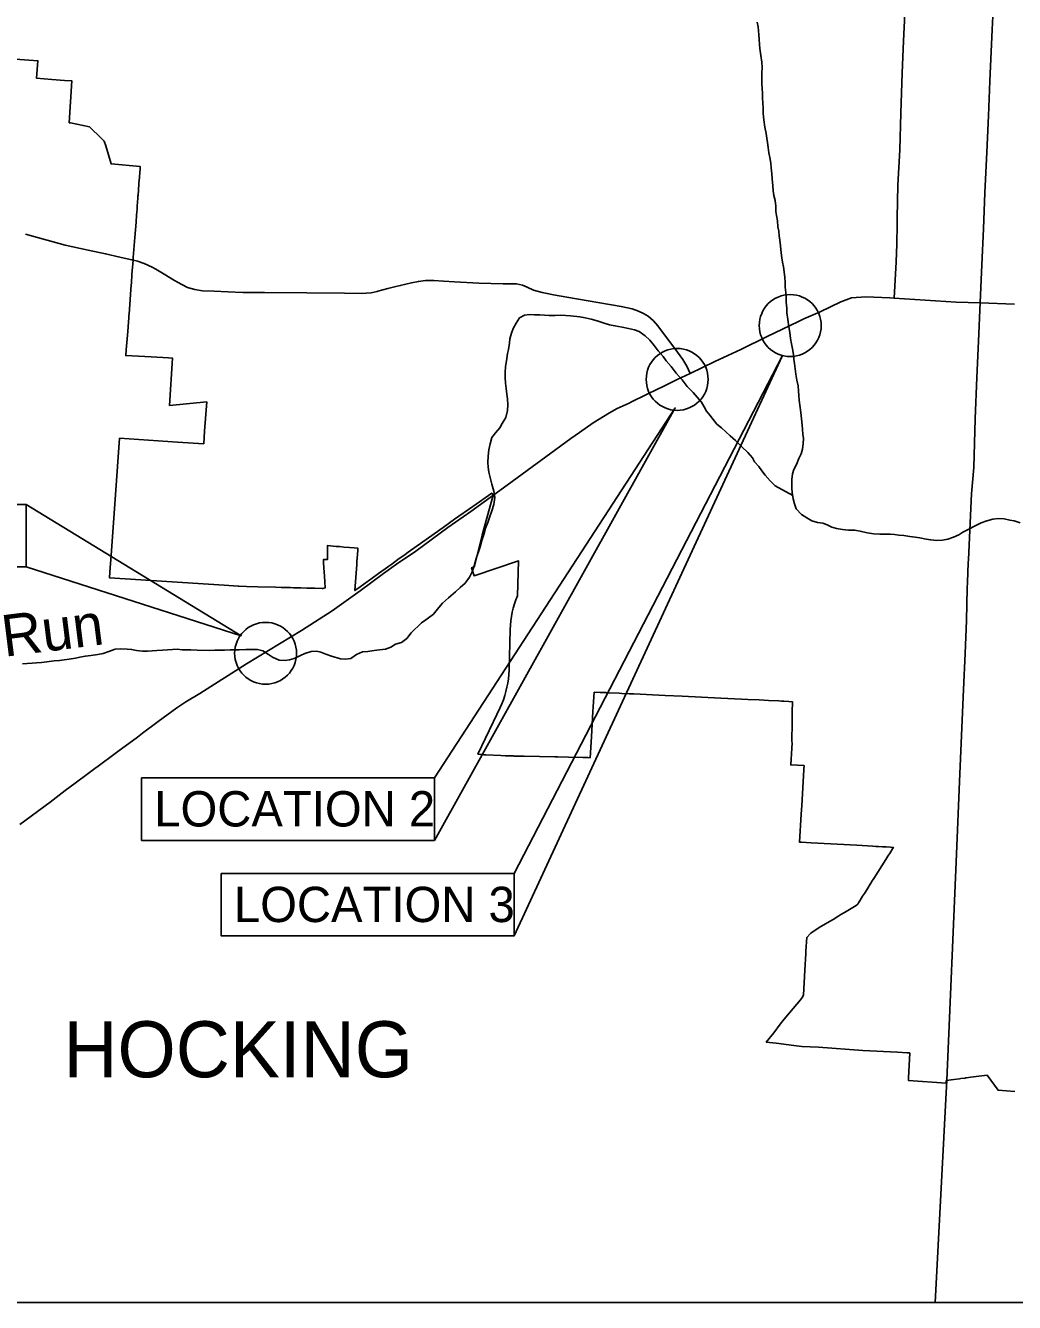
# Model space of a CAD drawing. Extents: x 0 to 34, y 0 to 22.
# Drawn here: x 4.86 to 9.62, y 8.99 to 15.13 of the extents above; entities that cross this region are included whole.
import ezdxf

# ---------------------------------------------------------------- set-up
doc = ezdxf.new("R2010")
doc.units = 0
for name, color, linetype in [('BR_P_Gen_Text', 7, 'Continuous'), ('Default', 7, 'Continuous'), ('GM_X_Corporation', 7, 'Continuous'), ('GM_X_Major_River', 7, 'Continuous'), ('GM_X_Minor_River', 7, 'Continuous'), ('GM_X_Minor_River_Text', 7, 'Continuous'), ('GM_X_State_Route', 7, 'Continuous'), ('GM_X_Township', 7, 'Continuous'), ('GM_X_Township_Text', 7, 'Continuous'), ('GM_X_US_Route', 7, 'Continuous'), ('SH_Text', 7, 'Continuous')]:
    doc.layers.add(name, color=color, linetype=linetype)

msp = doc.modelspace()

# ---------------------------------------------------------------- linework, layer by layer
at = {"layer": 'BR_P_Gen_Text'}
for points in [[(7.2085, 11.0538), (7.2085, 10.7536), (8.4986, 13.5428)], [(6.8251, 11.5138), (6.8251, 11.2136), (7.9848, 13.2947)], [(3.4525, 12.8303), (4.8613, 12.8303), (4.8613, 12.53), (3.4525, 12.53)], [(4.8613, 12.8303), (4.8613, 12.53), (5.8958, 12.1979)], [(5.4164, 11.5138), (6.8251, 11.5138), (6.8251, 11.2136), (5.4164, 11.2136)], [(5.7998, 11.0538), (7.2085, 11.0538), (7.2085, 10.7536), (5.7998, 10.7536)]]:
    msp.add_lwpolyline(points, close=True, dxfattribs=at)
at = {"layer": 'Default'}
for centre in [(8.5378, 13.6907), (7.9936, 13.4317), (6.0129, 12.1137)]:
    msp.add_circle(centre, 0.149, dxfattribs=at)
at = {"layer": 'GM_X_Corporation'}
msp.add_lwpolyline([(9.6181, 10.005), (9.5385, 10.0112), (9.4849, 10.0836), (9.4195, 10.0753), (9.3826, 10.0704), (9.3791, 10.07), (9.3592, 10.0673), (9.353, 10.0665), (9.3247, 10.0628), (9.2888, 10.0581), (9.2885, 10.0512), (9.2882, 10.0461), (9.107, 10.0584), (9.1076, 10.0704), (9.1131, 10.1912), (9.103, 10.1917), (9.1012, 10.1918), (9.0534, 10.1941), (8.8874, 10.2022), (8.6737, 10.2188), (8.5939, 10.2223), (8.5547, 10.2271), (8.47, 10.2373), (8.4385, 10.2412), (8.4224, 10.2431), (8.4593, 10.2878), (8.49, 10.3289), (8.4956, 10.3365), (8.5004, 10.3429), (8.5346, 10.3839), (8.587, 10.4467), (8.595, 10.4577), (8.6025, 10.4681), (8.6089, 10.5889), (8.6131, 10.6693), (8.6137, 10.6815), (8.6172, 10.747), (8.6351, 10.7654), (8.6374, 10.7677), (8.6441, 10.772), (8.6857, 10.7985), (8.6995, 10.8068), (8.7264, 10.823), (8.7439, 10.8336), (8.7712, 10.8499), (8.7822, 10.8566), (8.7994, 10.8669), (8.8479, 10.8961), (8.8607, 10.9038), (8.8625, 10.9066), (8.867, 10.9138), (8.8723, 10.9223), (8.8864, 10.9449), (8.895, 10.9586), (8.9059, 10.9762), (8.9223, 11.0024), (8.9256, 11.0077), (8.9289, 11.0129), (8.9295, 11.0139), (8.9402, 11.0307), (8.9594, 11.0611), (8.9787, 11.0914), (8.998, 11.1218), (9.0077, 11.1371), (9.0182, 11.1536), (9.0299, 11.1721), (9.0348, 11.1798), (9.021, 11.1806), (8.9995, 11.1818), (8.9826, 11.1827), (8.9628, 11.1839), (8.959, 11.1841), (8.9572, 11.1842), (8.9546, 11.1843), (8.9517, 11.1845), (8.9498, 11.1856), (8.9492, 11.1846), (8.936, 11.1854), (8.8578, 11.1898), (8.6392, 11.202), (8.5915, 11.2044), (8.5829, 11.2049), (8.5909, 11.3404), (8.5933, 11.382), (8.6034, 11.5526), (8.6036, 11.5558), (8.6043, 11.5733), (8.5405, 11.5766), (8.5458, 11.6575), (8.5474, 11.6818), (8.5457, 11.6906), (8.545, 11.6938), (8.5466, 11.7777), (8.5474, 11.8307), (8.5482, 11.8809), (8.5482, 11.8809), (8.531, 11.8818), (8.5073, 11.8831), (8.4953, 11.8837), (8.4833, 11.8843), (8.4335, 11.8869), (8.389, 11.8893), (8.3338, 11.8917), (8.3029, 11.8933), (8.2033, 11.8981), (8.0171, 11.9072), (7.9353, 11.9112), (7.7846, 11.9185), (7.7646, 11.9194), (7.7278, 11.921), (7.7143, 11.9216), (7.6664, 11.9236), (7.6594, 11.9239), (7.6544, 11.9241), (7.6497, 11.9243), (7.6425, 11.9246), (7.6238, 11.9254), (7.5946, 11.9267), (7.5932, 11.9047), (7.5917, 11.8809), (7.5902, 11.8569), (7.5886, 11.833), (7.581, 11.7117), (7.5747, 11.6115), (7.5636, 11.6117), (7.5403, 11.6122), (7.4715, 11.6137), (7.419, 11.6149), (7.4123, 11.615), (7.4054, 11.6152), (7.3305, 11.6169), (7.2579, 11.6185), (7.2288, 11.6191), (7.2192, 11.6193), (7.2144, 11.6194), (7.2098, 11.6195), (7.2037, 11.6197), (7.2, 11.6197), (7.1854, 11.6201), (7.1787, 11.6203), (7.1654, 11.6209), (7.1455, 11.6217), (7.0725, 11.6251), (7.0625, 11.6256), (7.0563, 11.6263), (7.0492, 11.6271), (7.0348, 11.6288), (7.108, 11.7825), (7.1097, 11.7861), (7.1412, 11.8523), (7.1497, 11.8712), (7.1572, 11.8905), (7.1639, 11.9101), (7.1697, 11.9301), (7.1745, 11.9502), (7.1785, 11.9706), (7.1814, 11.9912), (7.1834, 12.0118), (7.1845, 12.0325), (7.1904, 12.2282), (7.1915, 12.2491), (7.1935, 12.2699), (7.1965, 12.2906), (7.2003, 12.3111), (7.2051, 12.3315), (7.2108, 12.3516), (7.2174, 12.3714), (7.2249, 12.3909), (7.2304, 12.5581), (7.0166, 12.4871), (7.0103, 12.506), (7.004, 12.525), (7.0161, 12.529), (7.0275, 12.5738), (7.0486, 12.6569), (7.0554, 12.6816), (7.0623, 12.7064), (7.1039, 12.8572), (7.1075, 12.8702), (7.108, 12.8721), (7.11, 12.8735), (7.101, 12.8846), (7.0106, 12.8206), (6.9226, 12.7584), (6.8673, 12.7193), (6.7428, 12.6312), (6.7425, 12.631), (6.7422, 12.6308), (6.7109, 12.6084), (6.7107, 12.6082), (6.7105, 12.6081), (6.7103, 12.608), (6.6993, 12.6001), (6.6923, 12.595), (6.6825, 12.588), (6.6709, 12.5797), (6.6495, 12.5643), (6.628, 12.5489), (6.6197, 12.5429), (6.6066, 12.5335), (6.6001, 12.5288), (6.5888, 12.5207), (6.5886, 12.5205), (6.5884, 12.5204), (6.5882, 12.5203), (6.5569, 12.4978), (6.5567, 12.4976), (6.5565, 12.4975), (6.5563, 12.4974), (6.5259, 12.4755), (6.5083, 12.4629), (6.5034, 12.459), (6.4862, 12.4457), (6.4685, 12.4335), (6.4426, 12.4156), (6.4516, 12.5406), (6.4517, 12.5431), (6.4524, 12.5527), (6.4542, 12.5768), (6.4547, 12.5848), (6.4569, 12.615), (6.4572, 12.6194), (6.4394, 12.6209), (6.4171, 12.6228), (6.3901, 12.625), (6.3679, 12.6269), (6.3521, 12.6282), (6.3104, 12.6317), (6.3107, 12.6098), (6.3108, 12.6052), (6.3112, 12.5658), (6.2913, 12.5643), (6.2922, 12.5483), (6.2935, 12.5252), (6.2957, 12.4847), (6.2973, 12.4572), (6.2989, 12.4287), (6.2877, 12.4255), (6.2861, 12.4255), (6.2846, 12.4256), (6.2506, 12.4265), (6.2128, 12.4275), (6.211, 12.4276), (6.1827, 12.4284), (6.1822, 12.4284), (6.1647, 12.4289), (6.1467, 12.4294), (6.1326, 12.4298), (6.1311, 12.4298), (6.1228, 12.43), (6.0987, 12.4307), (6.0884, 12.431), (6.0604, 12.4318), (5.9748, 12.4341), (5.9215, 12.4356), (5.8836, 12.4367), (5.8814, 12.4367), (5.8141, 12.4411), (5.2611, 12.4775), (5.2631, 12.5042), (5.2691, 12.5865), (5.2906, 12.8769), (5.3103, 13.1485), (5.5889, 13.1303), (5.7149, 13.1223), (5.7193, 13.183), (5.7208, 13.2037), (5.7296, 13.3236), (5.5511, 13.3057), (5.5645, 13.5345), (5.5461, 13.5354), (5.4624, 13.5395), (5.4015, 13.5429), (5.3401, 13.5463), (5.3423, 13.5739), (5.3492, 13.6627), (5.3528, 13.708), (5.3542, 13.7255), (5.355, 13.7364), (5.3573, 13.7653), (5.3576, 13.7696), (5.3663, 13.8872), (5.3668, 13.894), (5.3699, 13.936), (5.3751, 14.006), (5.376, 14.0176), (5.3835, 14.114), (5.3893, 14.188), (5.392, 14.2233), (5.3929, 14.235), (5.3942, 14.2532), (5.3953, 14.2665), (5.3965, 14.283), (5.3982, 14.3055), (5.3988, 14.3129), (5.3992, 14.3184), (5.4011, 14.3428), (5.4033, 14.3727), (5.4036, 14.3763), (5.4056, 14.4025), (5.4076, 14.4289), (5.4087, 14.4435), (5.4097, 14.4556), (5.2703, 14.4688), (5.2437, 14.5549), (5.2367, 14.5776), (5.2229, 14.5911), (5.1662, 14.6462), (5.0739, 14.6656), (5.0682, 14.6668), (5.0807, 14.8675), (5.0449, 14.8704), (4.9835, 14.8752), (4.911, 14.8809), (4.9172, 14.9647), (4.7663, 14.9757)], dxfattribs=at)
at = {"layer": 'GM_X_Major_River'}
for points in [[(8.5131, 13.8989), (8.5122, 13.9213), (8.5081, 13.9493), (8.5049, 13.9732), (8.5, 13.9956), (8.4968, 14.0164), (8.4943, 14.0412), (8.4903, 14.074), (8.4878, 14.1012), (8.4853, 14.122), (8.4829, 14.1452), (8.4788, 14.1659), (8.4764, 14.1947), (8.4723, 14.2195), (8.4691, 14.2395), (8.4682, 14.2651), (8.4649, 14.2923), (8.4593, 14.3171), (8.456, 14.3395), (8.4536, 14.3626), (8.4503, 14.3962), (8.4486, 14.421), (8.4462, 14.4498), (8.4445, 14.4722), (8.4396, 14.4994), (8.4348, 14.521), (8.4315, 14.5482), (8.4291, 14.5714), (8.4258, 14.5921), (8.4218, 14.6153), (8.4153, 14.6449), (8.4104, 14.6809), (8.4072, 14.7105), (8.4071, 14.7369), (8.4054, 14.7625), (8.4046, 14.7849), (8.4037, 14.808), (8.4028, 14.8336), (8.4012, 14.8536), (8.401, 14.9064), (8.4026, 14.932), (8.4009, 14.9584), (8.3968, 14.9904), (8.392, 15.0232), (8.3903, 15.0432), (8.3886, 15.068), (8.3862, 15.0888), (8.3829, 15.1288), (8.3788, 15.1503)], [(9.6442, 12.741), (9.6155, 12.7506), (9.594, 12.7545), (9.5668, 12.76), (9.5397, 12.7623), (9.5134, 12.7598), (9.4848, 12.7517), (9.4561, 12.742), (9.425, 12.7259), (9.398, 12.7114), (9.3693, 12.6962), (9.3486, 12.6841), (9.3232, 12.6728), (9.2961, 12.6623), (9.2706, 12.6574), (9.2427, 12.6565), (9.214, 12.6596), (9.1917, 12.6636), (9.1614, 12.6691), (9.139, 12.673), (9.1135, 12.6761), (9.084, 12.68), (9.0609, 12.6823), (9.0402, 12.6847), (9.0194, 12.6862), (8.9987, 12.6869), (8.9684, 12.6876), (8.9397, 12.6891), (8.9078, 12.6938), (8.8743, 12.7017), (8.8472, 12.7064), (8.8185, 12.7063), (8.7898, 12.7087), (8.7611, 12.715), (8.7387, 12.7213), (8.7164, 12.7324), (8.6948, 12.7395), (8.6685, 12.7427), (8.6422, 12.7514), (8.6182, 12.7649), (8.5927, 12.7816), (8.5671, 12.8087), (8.5583, 12.8335), (8.5526, 12.8575), (8.5478, 12.8871), (8.5461, 12.9078), (8.5453, 12.9278), (8.5452, 12.9494), (8.5491, 12.9767), (8.5554, 12.9975), (8.5673, 13.0215), (8.58, 13.0503), (8.5903, 13.0736), (8.5974, 13.096), (8.6005, 13.1224), (8.6012, 13.1472), (8.5988, 13.168), (8.5963, 13.1912), (8.5955, 13.2112), (8.5914, 13.2424), (8.5889, 13.2728), (8.5857, 13.2968), (8.5816, 13.3319), (8.5791, 13.3543), (8.5783, 13.3743), (8.5758, 13.3999), (8.5702, 13.4279), (8.5645, 13.4575), (8.5612, 13.4823), (8.558, 13.5087), (8.5547, 13.5286), (8.5531, 13.5502), (8.5498, 13.571), (8.5434, 13.6022), (8.5393, 13.6286), (8.5353, 13.6566), (8.5312, 13.6838), (8.5263, 13.7197), (8.5222, 13.7525), (8.5214, 13.7741), (8.5189, 13.8037), (8.5188, 13.8269), (8.5172, 13.8501), (8.5139, 13.8757), (8.5131, 13.8989)]]:
    msp.add_lwpolyline(points, dxfattribs=at)
at = {"layer": 'GM_X_Minor_River'}
for points in [[(6.7631, 12.2607), (6.7846, 12.2743), (6.8212, 12.3023), (6.8459, 12.3335), (6.8651, 12.3544), (6.8937, 12.3808), (6.9264, 12.4096), (6.9487, 12.4296), (6.9734, 12.4505), (6.9949, 12.4793), (7.0077, 12.5049), (7.0172, 12.5353), (7.0268, 12.5705), (7.0451, 12.6257), (7.0531, 12.6569), (7.0634, 12.6857), (7.0706, 12.7153), (7.0817, 12.7425), (7.0929, 12.7713), (7.1024, 12.7985), (7.1112, 12.8297), (7.116, 12.8633), (7.112, 12.8937), (7.1016, 12.9273), (7.0936, 12.9593), (7.088, 12.9849), (7.0848, 13.0088), (7.0832, 13.032), (7.084, 13.0624), (7.088, 13.092), (7.0935, 13.1216), (7.1023, 13.152), (7.119, 13.1744), (7.1397, 13.1993), (7.1517, 13.2201), (7.1684, 13.2489), (7.1764, 13.2817), (7.1788, 13.3097), (7.1772, 13.3385), (7.174, 13.36), (7.17, 13.388), (7.1668, 13.4128), (7.1652, 13.44), (7.166, 13.4664), (7.1675, 13.4928), (7.1747, 13.5328), (7.1779, 13.556), (7.1826, 13.576), (7.1874, 13.6056), (7.189, 13.6264), (7.197, 13.6544), (7.2049, 13.676), (7.2185, 13.7024), (7.2344, 13.7272), (7.2583, 13.74), (7.283, 13.7441), (7.3069, 13.7417), (7.3332, 13.7417), (7.3556, 13.7401), (7.3771, 13.7394), (7.4058, 13.7394), (7.4345, 13.7402), (7.4807, 13.7379), (7.5246, 13.7323), (7.5517, 13.7276), (7.5804, 13.7212), (7.6083, 13.7132), (7.6417, 13.7029), (7.6688, 13.6941), (7.6944, 13.6901), (7.7286, 13.683), (7.7597, 13.6758), (7.7876, 13.6694), (7.8115, 13.6623), (7.8394, 13.6407), (7.8626, 13.6199), (7.8833, 13.5944), (7.9017, 13.5696), (7.9256, 13.5424), (7.9407, 13.5217), (7.9647, 13.4937), (7.9894, 13.4617), (8.0173, 13.4298), (8.0412, 13.3978), (8.0715, 13.3691), (8.0907, 13.3467), (8.1114, 13.3227), (8.1234, 13.3003), (8.1353, 13.2795), (8.1513, 13.2588), (8.1672, 13.238), (8.1848, 13.2164), (8.2071, 13.198), (8.2486, 13.1597), (8.2741, 13.1381), (8.3052, 13.1078), (8.3339, 13.0806), (8.3562, 13.0543), (8.3658, 13.0343), (8.3873, 13.0119), (8.4017, 12.9919)], [(8.4017, 12.9919), (8.4176, 12.9703), (8.4407, 12.9432), (8.4647, 12.92), (8.5501, 12.8726)], [(6.1066, 12.0784), (6.1274, 12.0823), (6.1506, 12.0885), (6.1803, 12.1034), (6.2019, 12.112), (6.2323, 12.1222), (6.2587, 12.1235), (6.2794, 12.1185), (6.3024, 12.1095), (6.3303, 12.1004), (6.3732, 12.0872), (6.398, 12.0854), (6.4235, 12.0883), (6.4508, 12.1073), (6.4797, 12.1207), (6.5045, 12.1228), (6.5348, 12.1266), (6.5612, 12.1311), (6.5907, 12.1333), (6.6156, 12.1434), (6.6381, 12.1577), (6.6669, 12.1662), (6.6934, 12.1852), (6.7136, 12.2115), (6.7631, 12.2607)], [(4.8431, 12.0629), (4.8655, 12.0651), (4.8887, 12.0665), (4.911, 12.0679), (4.935, 12.0693), (4.9597, 12.0722), (4.9949, 12.0775), (5.0205, 12.0797), (5.0428, 12.0827), (5.0668, 12.0857), (5.098, 12.0902), (5.1196, 12.0948), (5.146, 12.1002), (5.1723, 12.1039), (5.2059, 12.1084), (5.2307, 12.1122), (5.2587, 12.1224), (5.2883, 12.1341), (5.3147, 12.1347), (5.3466, 12.1336), (5.3681, 12.1326), (5.392, 12.1275), (5.4207, 12.1241), (5.4447, 12.1238), (5.4894, 12.1266), (5.5173, 12.1288), (5.5413, 12.1302), (5.5645, 12.1323), (5.5868, 12.1329), (5.6115, 12.1311), (5.6323, 12.1301), (5.6538, 12.1299), (5.6833, 12.128), (5.7408, 12.1275), (5.7679, 12.1281), (5.7935, 12.1294), (5.815, 12.1292), (5.8421, 12.1298), (5.8645, 12.1304), (5.886, 12.131), (5.9172, 12.1315), (5.9475, 12.132), (5.9738, 12.1326), (5.9993, 12.1259), (6.0263, 12.108), (6.0469, 12.095), (6.0779, 12.0803), (6.1066, 12.0784)]]:
    msp.add_lwpolyline(points, dxfattribs=at)
at = {"layer": 'GM_X_State_Route'}
for p in [(9.0168, 13.8239), (9.3361, 13.8036)]:
    msp.add_line(p, (9.0373, 13.8231), dxfattribs=at)
for points in [[(9.0531, 14.2085), (9.055, 14.3656), (9.0658, 14.5364), (9.0701, 14.7127), (9.0762, 14.9069), (9.0828, 15.0593), (9.0937, 15.2928), (9.0966, 15.4368), (9.0985, 15.4757)], [(9.0373, 13.8231), (9.0472, 13.9972), (9.0512, 14.0825), (9.0528, 14.1792), (9.0531, 14.2085)], [(4.8569, 14.1299), (5.0476, 14.0772), (5.1597, 14.0535), (5.2428, 14.0361), (5.3121, 14.0199), (5.3614, 14.0089)], [(5.3614, 14.0089), (5.3697, 14.0071), (5.3969, 14.0003), (5.4293, 13.9895), (5.4663, 13.9724), (5.4845, 13.9616), (5.5254, 13.9383), (5.5737, 13.9082), (5.6095, 13.8877), (5.6367, 13.8739), (5.6725, 13.864), (5.7088, 13.8584), (5.7658, 13.8565), (5.8309, 13.8527), (5.9038, 13.8504), (6.0071, 13.8493), (6.2121, 13.8478), (6.3921, 13.8463), (6.4724, 13.8455), (6.5213, 13.8485), (6.5498, 13.8551)], [(6.5498, 13.8551), (6.5538, 13.856), (6.6018, 13.8683), (6.6335, 13.8763), (6.661, 13.8828), (6.7147, 13.8961), (6.7485, 13.9034), (6.7829, 13.9076), (6.8227, 13.9082), (6.8686, 13.9046), (6.9217, 13.9003), (7.0392, 13.8947), (7.1569, 13.8915), (7.2208, 13.8913), (7.2495, 13.8843), (7.272, 13.8752), (7.3018, 13.8617), (7.344, 13.8493), (7.3608, 13.8459), (7.3982, 13.8392), (7.463, 13.8271), (7.7241, 13.782), (7.7772, 13.7709), (7.8082, 13.7594), (7.8319, 13.7489), (7.8534, 13.7353), (7.8798, 13.7134), (7.9006, 13.6897), (7.9331, 13.6457), (7.982, 13.5802), (8.0205, 13.528), (8.0409, 13.495), (8.0568, 13.4603)], [(8.5784, 13.7104), (8.6035, 13.7226), (8.6818, 13.7561), (8.7814, 13.8045), (8.8325, 13.8248)], [(8.8325, 13.8248), (8.902, 13.8285), (9.0168, 13.8239)], [(9.618, 13.7944), (9.4524, 13.7998), (9.3361, 13.8036)], [(8.0568, 13.4603), (8.1752, 13.5177), (8.3004, 13.5758), (8.4264, 13.6374), (8.5378, 13.6907), (8.5784, 13.7104)]]:
    msp.add_lwpolyline(points, dxfattribs=at)
at = {"layer": 'GM_X_Township'}
msp.add_lwpolyline([(9.2362, 8.9902), (9.2911, 10.0597), (9.3381, 11.1472), (9.3532, 11.4972), (9.3723, 11.9391), (9.3799, 12.1129), (9.3867, 12.271), (9.3892, 12.4268), (9.3905, 12.4565), (9.3942, 12.5485), (9.3954, 12.5655), (9.4104, 12.8809), (9.4219, 13.0084), (9.4274, 13.2411), (9.4362, 13.4407), (9.4438, 13.6155), (9.452, 13.8009), (9.4599, 13.9826), (9.4676, 14.1564), (9.4751, 14.329), (9.4837, 14.5242), (9.4914, 14.7), (9.4988, 14.8672), (9.5097, 15.1156), (9.517, 15.2769)], dxfattribs=at)
at = {"layer": 'GM_X_US_Route'}
for p, q in [((9.0168, 13.8239), (9.0373, 13.8231)), ((9.0373, 13.8231), (9.3361, 13.8036)), ((7.7742, 13.323), (7.9054, 13.3873)), ((5.2071, 11.5707), (5.2893, 11.6318))]:
    msp.add_line(p, q, dxfattribs=at)
for points in [[(8.5784, 13.7104), (8.6035, 13.7226), (8.6818, 13.7561), (8.7814, 13.8045), (8.8325, 13.8248)], [(8.8325, 13.8248), (8.902, 13.8285), (9.0168, 13.8239)], [(9.3361, 13.8036), (9.4524, 13.7998), (9.618, 13.7944)], [(8.0568, 13.4603), (8.1752, 13.5177), (8.3004, 13.5758), (8.4264, 13.6374), (8.5378, 13.6907), (8.5784, 13.7104)], [(7.9054, 13.3873), (7.9129, 13.391), (7.9936, 13.4317), (8.0568, 13.4603)], [(7.5894, 13.222), (7.6684, 13.2708), (7.7049, 13.2912), (7.7629, 13.3175), (7.7742, 13.323)], [(7.2473, 12.976), (7.3853, 13.0774), (7.4827, 13.1474), (7.523, 13.1756), (7.5894, 13.222)], [(6.4343, 12.3908), (6.4676, 12.4145), (6.5798, 12.4973), (6.6437, 12.5428), (6.7359, 12.6057), (6.8904, 12.7189), (7.0009, 12.7956), (7.1758, 12.9234), (7.2473, 12.976)], [(5.4211, 11.7293), (5.4959, 11.7853), (5.5856, 11.8512), (5.6291, 11.8802), (5.6969, 11.9204), (5.9217, 12.0628), (6.1862, 12.2242), (6.3329, 12.3182), (6.4343, 12.3908)], [(5.2893, 11.6318), (5.3024, 11.6415), (5.3962, 11.7107), (5.4211, 11.7293)], [(4.8306, 11.2894), (4.9757, 11.3977), (5.049, 11.453), (5.0966, 11.4884), (5.1596, 11.5348), (5.1916, 11.559), (5.2071, 11.5707)]]:
    msp.add_lwpolyline(points, dxfattribs=at)
at = {"layer": 'SH_Text'}
msp.add_lwpolyline([(2.5702, 20.5443), (15.6971, 20.5443), (15.6971, 8.9902), (2.5702, 8.9902)], close=True, dxfattribs=at)

# ---------------------------------------------------------------- texts
at = {"layer": 'BR_P_Gen_Text'}
for s, p in [('LOCATION 2', (5.4771, 11.2804)), ('LOCATION 3', (5.8605, 10.8204))]:
    msp.add_text(s, height=0.17, dxfattribs=at).set_placement(p)
at = {"layer": 'GM_X_Minor_River_Text'}
msp.add_text('Run', height=0.19974, rotation=7.1583, dxfattribs=at).set_placement((4.7557, 12.0966))
at = {"layer": 'GM_X_Township_Text'}
msp.add_text('HOCKING', height=0.26966, rotation=0.00001, dxfattribs=at).set_placement((5.0397, 10.0736))

doc.saveas('drawing.dxf')
